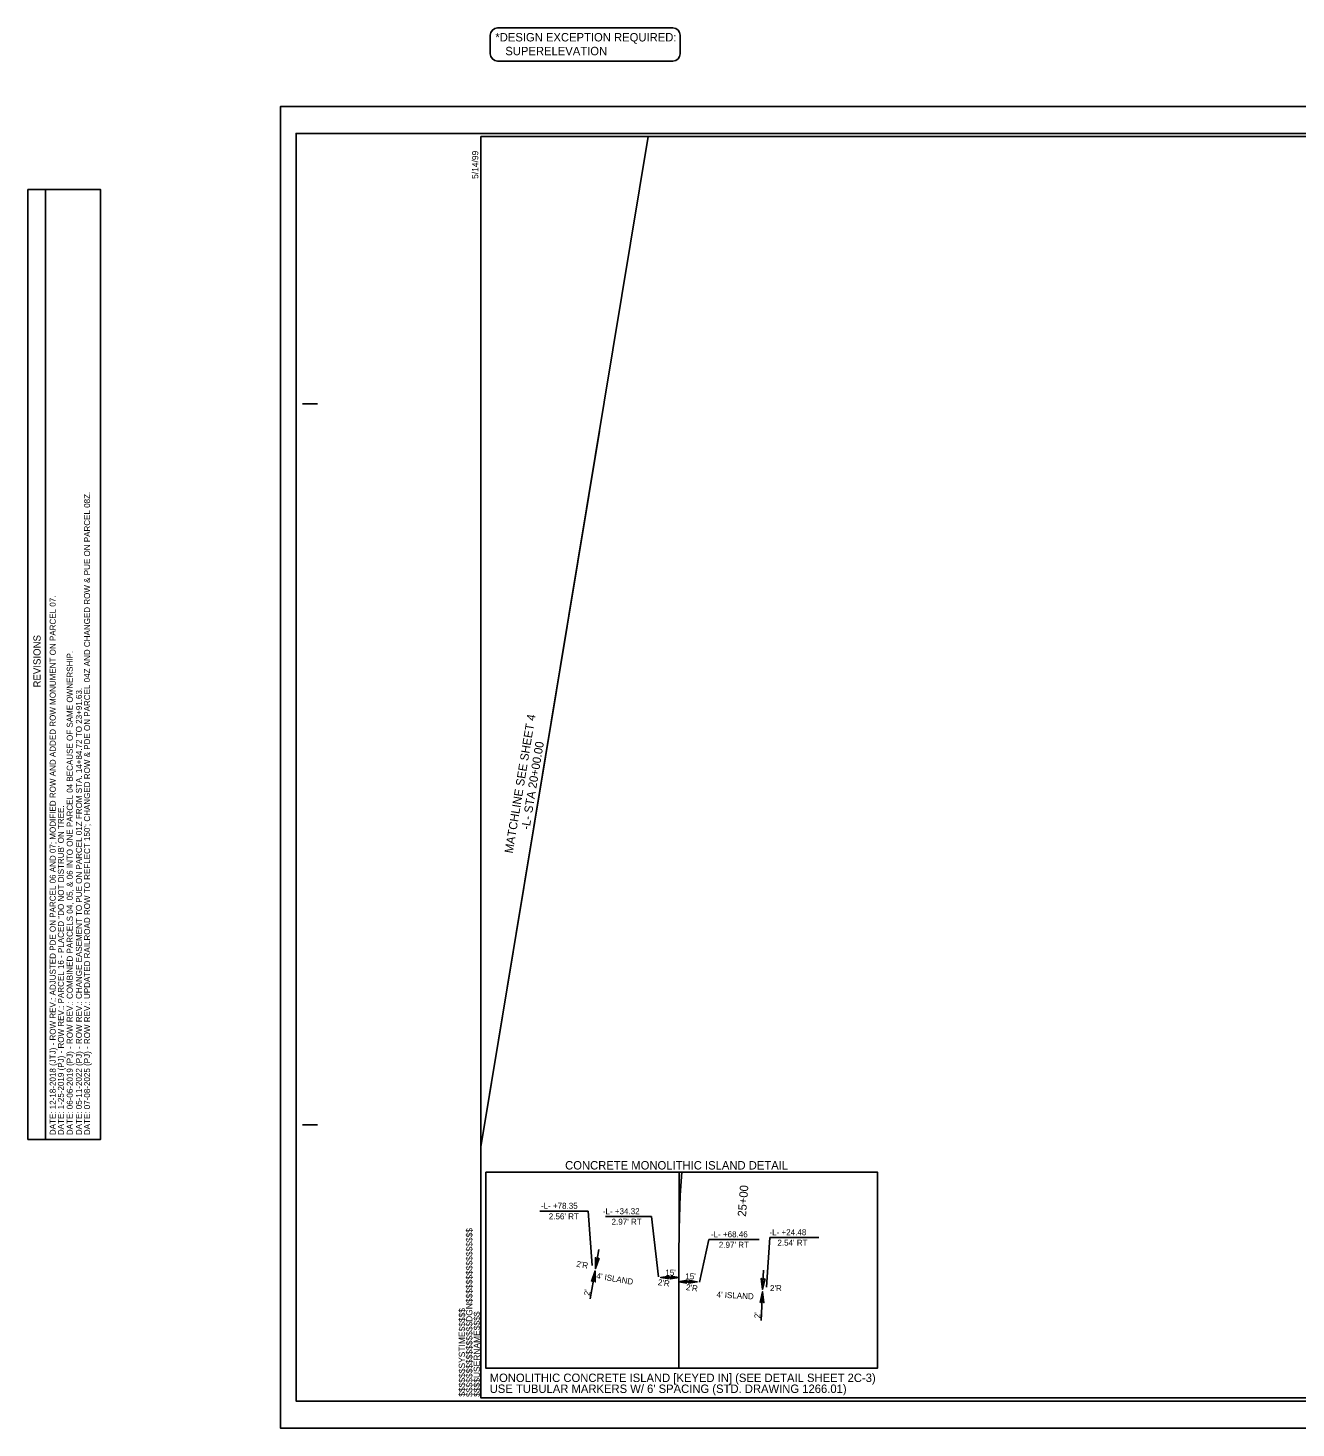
# Model space of a CAD drawing. Extents: x 1756263 to 1758375, y 736518 to 737683.
# Drawn here: x 1756263 to 1757319, y 736518 to 737683 of the extents above; entities that cross this region are included whole.
import ezdxf

# ---------------------------------------------------------------- set-up
doc = ezdxf.new("R2010")
doc.units = 0
for name, color, linetype in [('Default', 7, 'Continuous'), ('Matchline', 7, 'Continuous'), ('Matchline Text', 7, 'Continuous'), ('Old_Level_10', 7, 'Continuous'), ('Old_Level_18', 7, 'Continuous'), ('Old_Level_38', 7, 'Continuous'), ('Prop Dimension', 7, 'Continuous'), ('Prop DSN Text', 7, 'Continuous'), ('Prop Horizontal Alignment Tick Label', 7, 'Continuous'), ('Prop Terminator CELL', 7, 'Continuous'), ('Scratch_Level_3', 7, 'Continuous'), ('Sheet Block Revision CELL', 7, 'Continuous'), ('Sheet Border Standard 30in CELL', 7, 'Continuous'), ('Sheet Clip Boundary CELL', 7, 'Continuous'), ('Sheet Cutting Line CELL', 7, 'Continuous'), ('Sheet Plot Border Inside CELL', 7, 'Continuous'), ('Sheet Plot Border Outside CELL', 7, 'Continuous')]:
    doc.layers.add(name, color=color, linetype=linetype)

msp = doc.modelspace()

# ---------------------------------------------------------------- linework, layer by layer
at = {"layer": 'Default'}
for points in [[(1756805.3, 736660.5), (1756805.6, 736683.6), (1756806.5, 736711.4), (1756807.7, 736730.8)], [(1756805.5, 736676.6), (1756805.5, 736730.8)], [(1756805.3, 736660.5), (1756805.4, 736609.4), (1756805.4, 736567.4)]]:
    msp.add_lwpolyline(points, dxfattribs=at)
at = {"layer": 'Matchline'}
msp.add_line((1756640.5, 736751.7), (1756739.1, 737347.5), dxfattribs=at)
at = {"layer": 'Old_Level_10'}
msp.add_lwpolyline([(1756644.7, 736730.8), (1756970.7, 736730.8), (1756970.7, 736567.4), (1756644.7, 736567.4)], close=True, dxfattribs=at)
msp.add_lwpolyline([(1756644.7, 736730.8), (1756970.7, 736730.8), (1756970.7, 736567.4), (1756644.7, 736567.4)], close=True, dxfattribs=at)
at = {"layer": 'Old_Level_18'}
for p, q in [((1756648.3, 737677.1), (1756648.3, 737661.6)), ((1756654.3, 737683.1), (1756800.4, 737683.1)), ((1756806.4, 737677.1), (1756806.4, 737661.6)), ((1756654.3, 737655.6), (1756800.4, 737655.6))]:
    msp.add_line(p, q, dxfattribs=at)
for centre, start, end in [((1756654.3, 737677.1), 90, 180), ((1756800.4, 737677.1), 0, 90), ((1756654.3, 737661.6), 180, 270), ((1756800.4, 737661.6), 270, 0)]:
    msp.add_arc(centre, 6, start, end, dxfattribs=at)
at = {"layer": 'Prop Dimension'}
for p, q in [((1756729.9, 736698.3), (1756689.6, 736698.3)), ((1756729.9, 736698.3), (1756733.2, 736652.9)), ((1756782.5, 736693.8), (1756744.3, 736693.8)), ((1756782.5, 736693.8), (1756788.4, 736643.6)), ((1756830.3, 736674.6), (1756822.4, 736639.1)), ((1756872.1, 736674.6), (1756830.3, 736674.6)), ((1756881, 736676.4), (1756878.4, 736634.9)), ((1756921.9, 736676.4), (1756881, 736676.4)), ((1756735.9, 736650.4), (1756738.7, 736666.4)), ((1756731.6, 736625.3), (1756735.6, 736648.5)), ((1756875.1, 736633.1), (1756875.9, 736649)), ((1756790.4, 736643.4), (1756790.3, 736642.6)), ((1756790.4, 736643.4), (1756790.3, 736642.6)), ((1756805.4, 736643), (1756790.4, 736643)), ((1756805.4, 736643), (1756790.4, 736643)), ((1756805.4, 736639.5), (1756820.4, 736639.5)), ((1756805.4, 736639.5), (1756820.4, 736639.5)), ((1756820.4, 736638.8), (1756820.4, 736639.9)), ((1756820.4, 736638.8), (1756820.4, 736639.9)), ((1756873.9, 736607.3), (1756875, 736631.1))]:
    msp.add_line(p, q, dxfattribs=at)
at = {"layer": 'Prop Terminator CELL'}
for points in [[(1756739, 736659), (1756735.9, 736650.4), (1756735.9, 736659.6), (1756737.3, 736658.2)], [(1756732.6, 736639.8), (1756735.6, 736648.5), (1756735.7, 736639.3), (1756734.3, 736640.7)], [(1756797.2, 736641.8), (1756790.4, 736643), (1756797.2, 736644.2), (1756796.3, 736643)], [(1756792.6, 736642.6), (1756790.4, 736643), (1756792.6, 736643.4), (1756792.3, 736643)], [(1756798.6, 736644.2), (1756805.4, 736643), (1756798.5, 736641.8), (1756799.4, 736643)], [(1756803.1, 736643.4), (1756805.4, 736643), (1756803.1, 736642.6), (1756803.4, 736643)], [(1756812.1, 736638.3), (1756805.4, 736639.5), (1756812.2, 736640.7), (1756811.3, 736639.5)], [(1756807.6, 736639.1), (1756805.4, 736639.5), (1756807.6, 736639.9), (1756807.3, 736639.5)], [(1756813.6, 736640.7), (1756820.4, 736639.5), (1756813.5, 736638.3), (1756814.4, 736639.5)], [(1756877.1, 736642), (1756875.1, 736633.1), (1756874, 736642.2), (1756875.5, 736641)], [(1756873.1, 736622.2), (1756875, 736631.1), (1756876.2, 736622), (1756874.7, 736623.2)]]:
    msp.add_lwpolyline(points, close=True, dxfattribs=at)
at = {"layer": 'Scratch_Level_3'}
msp.add_lwpolyline([(1756640.5, 736542.7), (1758140.3, 736542.7), (1758140.3, 737295.2), (1757940.5, 737295.2), (1757940.5, 737592.7), (1756640.5, 737592.7)], close=True, dxfattribs=at)
at = {"layer": 'Sheet Block Revision CELL'}
msp.add_line((1756277.8, 736757.9), (1756277.8, 737548.6), dxfattribs=at)
msp.add_lwpolyline([(1756263.3, 736757.9), (1756263.3, 737548.6), (1756323.8, 737548.6), (1756323.8, 736757.9)], close=True, dxfattribs=at)
at = {"layer": 'Sheet Border Standard 30in CELL'}
for p, q in [((1756641.5, 737592.7), (1756641.5, 737592.7)), ((1756492, 737370.2), (1756504.5, 737370.2)), ((1756492, 736770.2), (1756504.5, 736770.2))]:
    msp.add_line(p, q, dxfattribs=at)
msp.add_lwpolyline([(1758140.5, 737592.7), (1756640.5, 737592.7), (1756640.5, 736542.7), (1758140.5, 736542.7)], close=True, dxfattribs=at)
at = {"layer": 'Sheet Clip Boundary CELL'}
msp.add_lwpolyline([(1756640.5, 736751.7), (1756640.5, 736542.7), (1758096.4, 736542.7), (1758075, 737295.2), (1757940.5, 737295.2), (1757940.5, 737592.7), (1756779.7, 737592.7)], close=True, dxfattribs=at)
at = {"layer": 'Sheet Cutting Line CELL'}
for p, q in [((1758157.5, 737617.7), (1756473.5, 737617.7)), ((1756473.5, 737617.7), (1756473.5, 736517.7)), ((1756473.5, 736517.7), (1758157.5, 736517.7))]:
    msp.add_line(p, q, dxfattribs=at)
at = {"layer": 'Sheet Plot Border Inside CELL'}
msp.add_lwpolyline([(1758153, 737595.3), (1756486.5, 737595.3), (1756486.5, 736540.2), (1758153, 736540.2)], close=True, dxfattribs=at)
at = {"layer": 'Sheet Plot Border Outside CELL'}
msp.add_lwpolyline([(1758157.5, 737617.7), (1756473.5, 737617.7), (1756473.5, 736517.7), (1758157.5, 736517.7)], close=True, dxfattribs=at)

# ---------------------------------------------------------------- texts
at = {"layer": 'Matchline Text'}
for s, p in [('MATCHLINE SEE SHEET 4 ', (1756667, 736995.7)), ('-L- STA 20+00.00', (1756680.9, 737015.4))]:
    msp.add_text(s, height=7, rotation=80.6079, dxfattribs=at).set_placement(p)
at = {"layer": 'Old_Level_38'}
for s, p in [('*DESIGN EXCEPTION REQUIRED: ', (1756652.5, 737671.9)), ('SUPERELEVATION', (1756660.8, 737660.4))]:
    msp.add_text(s, height=7, rotation=359.995, dxfattribs=at).set_placement(p)
at = {"layer": 'Prop Dimension'}
for s, p in [('-L- +78.35', (1756690.4, 736700.2)), ("2.56' RT", (1756697, 736691.4)), ('-L- +34.32', (1756742, 736695.7)), ("2.97' RT", (1756749.3, 736686.9)), ('-L- +24.48', (1756880.8, 736678.2)), ('-L- +68.46', (1756832, 736676.5)), ("2.97' RT", (1756838.6, 736667.7)), ("2.54' RT", (1756887.4, 736669.5))]:
    msp.add_text(s, height=5, dxfattribs=at).set_placement(p)
for s, height, rotation, p in [("2'R", 5, 349.5707, (1756719.6, 736652.1)), ("15'", 5, 1.0157, (1756794.1, 736644.5)), ("4' ISLAND", 5, 350.2531, (1756736.3, 736642.1)), ("2'R", 5, 352.096, (1756787.6, 736636.7)), ("15'", 5, 1.0157, (1756810.8, 736641.4)), ("2'R", 5, 352.096, (1756811, 736632.6)), ("2'R", 5, 359.658, (1756881.2, 736631.7)), ("2'", 5, 80.2531, (1756731.1, 736627.6)), ("4' ISLAND", 5, 357.0113, (1756836.6, 736626.4)), ("2'", 5, 87.3174, (1756873.1, 736609)), ("USE TUBULAR MARKERS W/ 6' SPACING (STD. DRAWING 1266.01)", 7, 360, (1756647.8, 736546.9)), ('MONOLITHIC CONCRETE ISLAND [KEYED IN] (SEE DETAIL SHEET 2C-3)', 7, 360, (1756647.8, 736556))]:
    msp.add_text(s, height=height, rotation=rotation, dxfattribs=at).set_placement(p)
at = {"layer": 'Prop DSN Text'}
msp.add_text('CONCRETE MONOLITHIC ISLAND DETAIL', height=7, rotation=359.9997, dxfattribs=at).set_placement((1756710.6, 736732.9))
at = {"layer": 'Prop Horizontal Alignment Tick Label'}
msp.add_text('25+00', height=7, rotation=85.4915, dxfattribs=at).set_placement((1756861.2, 736693.4))
at = {"layer": 'Sheet Block Revision CELL'}
for s, height, p in [("DATE: 07-08-2025 (PJ) - ROW REV.: UPDATED RAILROAD ROW TO REFLECT 150'; CHANGED ROW & PDE ON PARCEL 04Z AND CHANGED ROW & PUE ON PARCEL 08Z.  ", 5, (1756315, 736761.5)), ('DATE: 12-18-2018 (JTJ) - ROW REV.: ADJUSTED PDE ON PARCEL 06 AND 07; MODIFIED ROW AND ADDED ROW MONUMENT ON PARCEL 07.', 5, (1756286.4, 736761.5)), ('REVISIONS', 6, (1756273.8, 737134.1)), ('DATE: 06-06-2019 (PJ) - ROW REV.: COMBINED PARCELS 04, 05, & 06 INTO ONE PARCEL 04 BECAUSE OF SAME OWNERSHIP.', 5, (1756300.6, 736761.5)), ('DATE: 05-11-2022 (PJ) - ROW REV.: CHANGE EASEMENT TO PUE ON PARCEL 01Z FROM STA. 14+84.72 TO 23+91.63. ', 5, (1756308.2, 736761.5)), ('DATE: 1-25-2019 (PJ) - ROW REV.: PARCEL 16 - PLACED "DO NOT DISTRUB\' ON TREE.', 5, (1756293.2, 736761.5))]:
    msp.add_text(s, height=height, rotation=90, dxfattribs=at).set_placement(p)
at = {"layer": 'Sheet Border Standard 30in CELL'}
for s, p in [('5/14/99', (1756638.3, 737557.5)), ('$$$$$$$$$$$$$$$$DGN$$$$$$$$$$$$$$$$', (1756633.4, 736543.6)), ('$$$$$$SYSTIME$$$$$', (1756627.3, 736543.8)), ('$$$$USERNAME$$$$', (1756639.7, 736543.7))]:
    msp.add_text(s, height=5.25, rotation=90, dxfattribs=at).set_placement(p)

doc.saveas('drawing.dxf')
